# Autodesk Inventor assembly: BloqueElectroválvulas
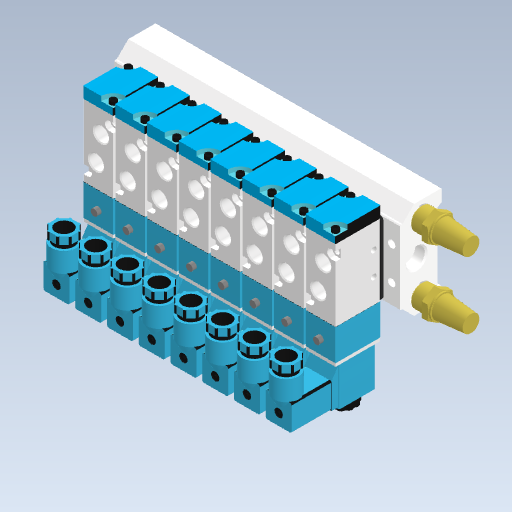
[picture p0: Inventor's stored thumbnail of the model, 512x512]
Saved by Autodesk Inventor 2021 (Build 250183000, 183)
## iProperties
Created: 2021-02
Part Number: BloqueElectroválvulas
Document SubType Name: Assembly
Designer: ATOUZA
Author: ATOUZA
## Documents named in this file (5)
- D:\01 Paralaia\Grupos de Traballo\GT Maquetas\CAD 3D\E_Medida\Electroválvulas\BloqueElectroválvulas.iam
- D:\01 Paralaia\Grupos de Traballo\GT Maquetas\CAD 3D\E_Medida\Electroválvulas\Base 8\manifold_100m-8f.iam
- D:\01 Paralaia\Grupos de Traballo\GT Maquetas\CAD 3D\E_Medida\Electroválvulas\Base 8\manifold_100m-8f_02.ipt
- D:\01 Paralaia\Grupos de Traballo\GT Maquetas\CAD 3D\E_Medida\Electroválvulas\soleniod_valve_4v110-06-a.ipt
- D:\01 Paralaia\Grupos de Traballo\GT Maquetas\CAD 3D\E_Medida\Electroválvulas\muffler_an201-02.ipt
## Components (19 placed, 4 different names)
1. manifold_100m-8f:1 [sub-assembly] — Insertar:1, Insertar:2, Insertar:3, Insertar:4
2. muffler_an201-02:1 — Insertar:3
3. muffler_an201-02:2 — Insertar:4
4. manifold_100m-8f_02:2 — Coincidencia:1, Insertar:1, Insertar:2, Nivelación:1, Nivelación:2
5. manifold_100m-8f_02:3
6. manifold_100m-8f_02:4
7. manifold_100m-8f_02:5
8. manifold_100m-8f_02:6
9. manifold_100m-8f_02:7
10. manifold_100m-8f_02:8
11. manifold_100m-8f_02:9
12. soleniod_valve_4v110-06-a:1 — Coincidencia:1, Nivelación:1, Nivelación:2
13. soleniod_valve_4v110-06-a:2
14. soleniod_valve_4v110-06-a:3
15. soleniod_valve_4v110-06-a:4
16. soleniod_valve_4v110-06-a:5
17. soleniod_valve_4v110-06-a:6
18. soleniod_valve_4v110-06-a:7
19. soleniod_valve_4v110-06-a:8
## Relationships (7: Insert 4, Flush 2, Mate 1)
- Coincidencia:1 [Mate]: manifold_100m-8f_02:2 ↔ soleniod_valve_4v110-06-a:1
- Insertar:1: manifold_100m-8f:1 ↔ manifold_100m-8f_02:2
- Insertar:2: manifold_100m-8f:1 ↔ manifold_100m-8f_02:2
- Nivelación:1 [Flush]: manifold_100m-8f_02:2 ↔ soleniod_valve_4v110-06-a:1
- Nivelación:2 [Flush]: manifold_100m-8f_02:2 ↔ soleniod_valve_4v110-06-a:1
- Insertar:3: manifold_100m-8f:1 ↔ muffler_an201-02:1
- Insertar:4: manifold_100m-8f:1 ↔ muffler_an201-02:2
